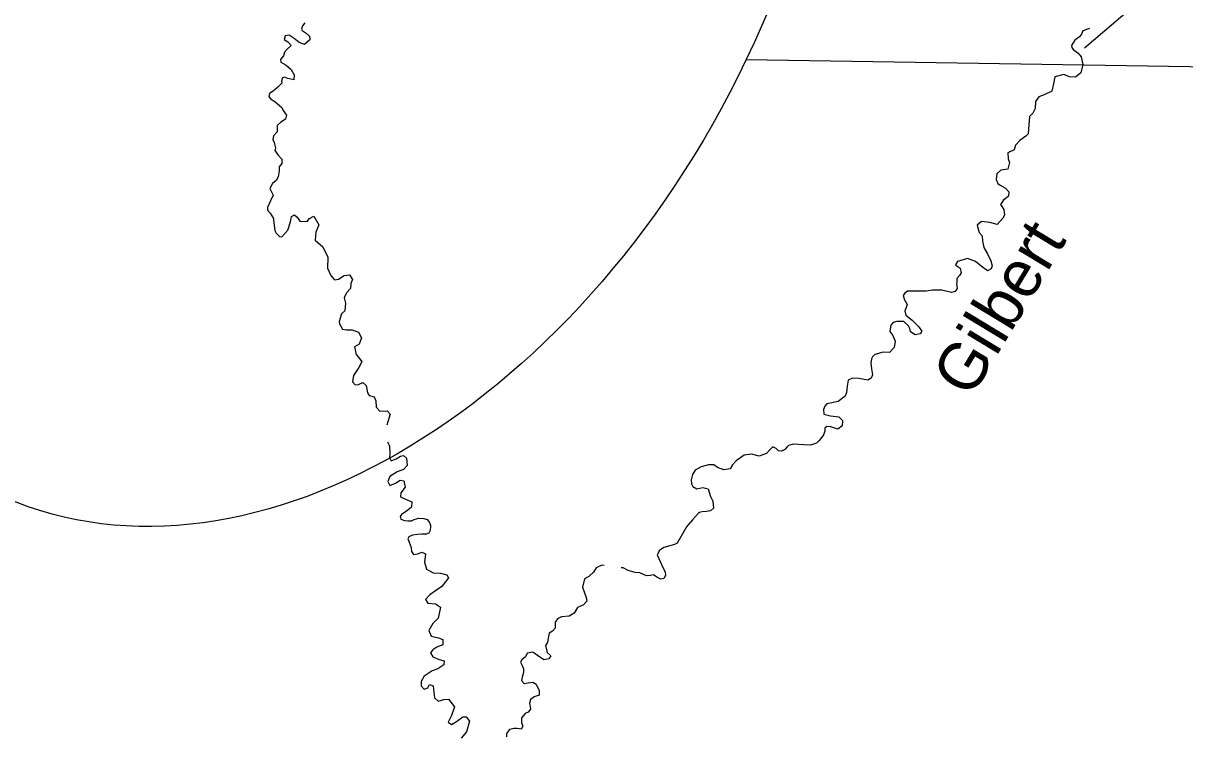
# Model space of a CAD drawing. Extents: x -492261 to -432772, y 1441225 to 1452922.
# Drawn here: x -459623.3 to -459493.5, y 1451796.7 to 1451876.1 of the extents above; entities that cross this region are included whole.
import ezdxf

# ---------------------------------------------------------------- set-up
doc = ezdxf.new("R2010")
doc.units = 0
doc.layers.add('Default', color=7, linetype='Continuous')

msp = doc.modelspace()

# ---------------------------------------------------------------- linework, layer by layer
at = {"layer": 'Default'}
for p, q in [((-459499.71, 1451877.6), (-459504.74, 1451873.32)), ((-459542.51, 1451872.05), (-459085.31, 1451864.81))]:
    msp.add_line(p, q, dxfattribs=at)
for points in [[(-459591.82, 1451876.14), (-459592.08, 1451875.81), (-459592.18, 1451875.45), (-459592.11, 1451875.29), (-459591.66, 1451875.01), (-459591.28, 1451874.67), (-459591.24, 1451874.24), (-459591.86, 1451873.75), (-459592.45, 1451873.97), (-459592.98, 1451874.41), (-459593.55, 1451874.78), (-459594.01, 1451874.7), (-459594.12, 1451874.3), (-459593.69, 1451874.02), (-459593.34, 1451873.63), (-459593.77, 1451873.2), (-459594.09, 1451872.88), (-459594.19, 1451872.45), (-459594.54, 1451872.07), (-459594.48, 1451871.75), (-459593.9, 1451871.42), (-459593.32, 1451870.94), (-459593.01, 1451870.35), (-459593.02, 1451869.78), (-459593.72, 1451869.92), (-459594.07, 1451870.08), (-459594.29, 1451870.01), (-459594.42, 1451869.65), (-459594.39, 1451869.41), (-459594.81, 1451868.95), (-459595.35, 1451868.53), (-459595.75, 1451868.27), (-459595.84, 1451867.92), (-459595.64, 1451867.65), (-459595.15, 1451867.36), (-459594.36, 1451866.71), (-459594.21, 1451866.37), (-459593.86, 1451865.86), (-459593.96, 1451865.39), (-459594.48, 1451865.07), (-459594.89, 1451864.67)], [(-459504.18, 1451875.53), (-459504.92, 1451875.27), (-459505.08, 1451874.9), (-459505.3, 1451874.57), (-459505.81, 1451874.21), (-459506.19, 1451873.62), (-459506.14, 1451873.4), (-459506, 1451873.16), (-459505.45, 1451872.75), (-459505.13, 1451872.34), (-459504.93, 1451871.49), (-459505.16, 1451870.57), (-459505.76, 1451870.09), (-459506.41, 1451870.11), (-459507.06, 1451870.37), (-459508.05, 1451870.12), (-459508.2, 1451869.33), (-459508.38, 1451868.53), (-459509.26, 1451868.11), (-459509.84, 1451867.9), (-459510.23, 1451867.37), (-459510.24, 1451866.58), (-459510.52, 1451866.07), (-459510.88, 1451865.68), (-459510.94, 1451864.75), (-459511.02, 1451863.76), (-459511.28, 1451863.48), (-459511.97, 1451863.01), (-459512.43, 1451862.49), (-459512.61, 1451861.98), (-459513.29, 1451861.65), (-459513.25, 1451860.95), (-459513.1, 1451860.56), (-459513.31, 1451859.83), (-459514.08, 1451859.72), (-459514.54, 1451859.29), (-459514.59, 1451858.67), (-459514.42, 1451858.22), (-459514.17, 1451858.03), (-459513.55, 1451857.68), (-459513.18, 1451857.29), (-459513.24, 1451856.8), (-459513.82, 1451856.33), (-459514.13, 1451855.87), (-459513.75, 1451855.32), (-459513.66, 1451854.68), (-459513.85, 1451854.35), (-459514.5, 1451853.64), (-459515.33, 1451853.85), (-459516.26, 1451853.96), (-459516.72, 1451853.57), (-459516.49, 1451852.73), (-459516.17, 1451852.36), (-459516.15, 1451851.77), (-459515.97, 1451851.07), (-459515.57, 1451850.37), (-459515.2, 1451849.57), (-459515.07, 1451849.02), (-459515.17, 1451848.67), (-459515.58, 1451848.46), (-459516.29, 1451848.97), (-459516.9, 1451849.52), (-459517.79, 1451849.85), (-459518.94, 1451849.49), (-459519.13, 1451849.15), (-459518.95, 1451848.97), (-459518.64, 1451848.76), (-459518.52, 1451848.25), (-459518.7, 1451847.94), (-459519, 1451847.6), (-459519, 1451847.17), (-459519.02, 1451847.02), (-459518.97, 1451846.49), (-459519.18, 1451846.15), (-459519.6, 1451846.06), (-459520.66, 1451846.29), (-459521.71, 1451846.32), (-459522.42, 1451846.19), (-459523.69, 1451846.18), (-459524.49, 1451846.19), (-459524.83, 1451845.95), (-459524.99, 1451845.7), (-459524.84, 1451845.23), (-459524.56, 1451844.7), (-459524.67, 1451844.36), (-459524.81, 1451843.98), (-459524.68, 1451843.53)], [(-459594.89, 1451864.67), (-459594.89, 1451863.97), (-459595.29, 1451863.55), (-459595.38, 1451863.13), (-459595.24, 1451862.78), (-459595.1, 1451862.2), (-459595.15, 1451861.88), (-459594.79, 1451861.37), (-459594.38, 1451860.94), (-459594.38, 1451860.44), (-459594.69, 1451860.06), (-459594.69, 1451859.63), (-459594.8, 1451858.94), (-459595.01, 1451858.56), (-459595.42, 1451858.22), (-459595.73, 1451857.65), (-459595.5, 1451857.19), (-459595.34, 1451856.92), (-459595.63, 1451856.27), (-459595.98, 1451855.52), (-459595.99, 1451855.23), (-459595.66, 1451854.91), (-459595.3, 1451854.3), (-459595.3, 1451854.13), (-459595.16, 1451852.97), (-459595.02, 1451852.68), (-459594.64, 1451852.28), (-459594.36, 1451852.27), (-459593.69, 1451853.01), (-459593.42, 1451853.95), (-459593.28, 1451854.51), (-459592.96, 1451854.72), (-459592.67, 1451854.44), (-459592.37, 1451854), (-459591.54, 1451853.97), (-459591.29, 1451854.29), (-459590.79, 1451854.58), (-459590.24, 1451853.61), (-459590.56, 1451852.79), (-459590.65, 1451851.88), (-459589.79, 1451851.15), (-459589.22, 1451849.97), (-459589.26, 1451848.77), (-459588.89, 1451847.94), (-459588.48, 1451847.44), (-459588.05, 1451847.53), (-459587.41, 1451847.93), (-459586.81, 1451848.01), (-459586.5, 1451847.48), (-459586.67, 1451847.04), (-459586.71, 1451846.48), (-459587.16, 1451846.02), (-459587.4, 1451845.46), (-459587.26, 1451844.85), (-459587.33, 1451843.99), (-459587.7, 1451843.68), (-459587.97, 1451842.79), (-459587.94, 1451842.56), (-459587.61, 1451841.95), (-459587.15, 1451841.89), (-459586.52, 1451841.89), (-459585.81, 1451841.62), (-459585.49, 1451841), (-459585.74, 1451840.26), (-459586.27, 1451839.98), (-459586.07, 1451839.11), (-459585.81, 1451838.82), (-459585.44, 1451838.29), (-459585.76, 1451837.67), (-459586.39, 1451836.78), (-459586.47, 1451836.06), (-459586.2, 1451835.73), (-459585.8, 1451835.78), (-459585.34, 1451835.98), (-459584.97, 1451835.65), (-459584.81, 1451834.83), (-459584.63, 1451834.55), (-459584.07, 1451834.41), (-459583.86, 1451833.93), (-459583.83, 1451833.24), (-459583.42, 1451832.81), (-459582.61, 1451832.84), (-459582.27, 1451832.46), (-459582.54, 1451831.62), (-459582.66, 1451831.24)], [(-459524.68, 1451843.53), (-459524, 1451842.96), (-459523.28, 1451842.25), (-459522.92, 1451841.72), (-459523.11, 1451841.44), (-459523.66, 1451841.33), (-459524.17, 1451841.65), (-459524.24, 1451842.03), (-459524.38, 1451842.32), (-459524.9, 1451842.8), (-459525.68, 1451842.81), (-459526.11, 1451842.68), (-459526.37, 1451842.41), (-459526.49, 1451841.68), (-459526.16, 1451841.23), (-459525.87, 1451840.6), (-459526.01, 1451839.9), (-459526.52, 1451839.34), (-459527.22, 1451839.38), (-459528.15, 1451839.11), (-459528.42, 1451838.87), (-459528.51, 1451838.65), (-459528.61, 1451838.16), (-459528.54, 1451837.52), (-459528.41, 1451836.84), (-459528.55, 1451836.48), (-459528.95, 1451836.27), (-459529.95, 1451836.44), (-459530.64, 1451836.47), (-459531.12, 1451836.27), (-459531.24, 1451835.58), (-459531.31, 1451834.86), (-459531.45, 1451834.47), (-459532.26, 1451833.89), (-459533.51, 1451833.6), (-459533.73, 1451833.34), (-459533.89, 1451832.98), (-459533.84, 1451832.45), (-459533.09, 1451832.28), (-459532.19, 1451832.18), (-459531.78, 1451831.74), (-459531.79, 1451831.15), (-459532.27, 1451830.78), (-459533.07, 1451831.04), (-459533.52, 1451831.1), (-459533.75, 1451830.91), (-459533.75, 1451830.56), (-459533.89, 1451830.17), (-459534.17, 1451829.73), (-459534.4, 1451829.49), (-459534.67, 1451829.24), (-459535.33, 1451828.99), (-459536.07, 1451829.04), (-459537.22, 1451829.1), (-459537.81, 1451828.96), (-459537.95, 1451828.81), (-459538.22, 1451828.51), (-459538.58, 1451828.32), (-459538.93, 1451828.35), (-459539.19, 1451828.64), (-459539.54, 1451828.8), (-459539.93, 1451828.45), (-459540.25, 1451828.08), (-459541.07, 1451827.78), (-459541.91, 1451828.01), (-459542.75, 1451827.9), (-459543.64, 1451827.25), (-459544.04, 1451826.79), (-459544.3, 1451826.36), (-459545.03, 1451826.23), (-459545.71, 1451826.52), (-459546.13, 1451826.79), (-459546.73, 1451826.8), (-459547.55, 1451826.58), (-459548.2, 1451826.22), (-459548.5, 1451825.71), (-459548.66, 1451825.14), (-459548.62, 1451824.68), (-459548.49, 1451824.4), (-459548.03, 1451824.12), (-459547.38, 1451824.26), (-459546.78, 1451824.11), (-459546.52, 1451823.27), (-459546.25, 1451822.73), (-459546.16, 1451821.98), (-459546.49, 1451821.66), (-459546.96, 1451821.61), (-459547.45, 1451821.57), (-459547.72, 1451821.48), (-459547.85, 1451821.39), (-459548.53, 1451820.68), (-459549, 1451820.12), (-459549.2, 1451819.87)], [(-459582.57, 1451829.37), (-459582.36, 1451828.94), (-459582.31, 1451828.06), (-459582.37, 1451827.61), (-459582.15, 1451827.25), (-459581.62, 1451827.47), (-459581.12, 1451827.78), (-459580.79, 1451827.83), (-459580.46, 1451827.55), (-459580.38, 1451826.74), (-459580.8, 1451826.28), (-459581.51, 1451826.02), (-459582.31, 1451825.5), (-459582.54, 1451824.95)], [(-459582.54, 1451824.95), (-459582.33, 1451824.51), (-459581.69, 1451824.74), (-459581.16, 1451825.08), (-459580.74, 1451825), (-459580.6, 1451824.3), (-459581.1, 1451823.66), (-459581.11, 1451823.23), (-459580.58, 1451822.97), (-459579.87, 1451822.68), (-459579.91, 1451822.07), (-459580.49, 1451821.59), (-459581.01, 1451821.27), (-459581.17, 1451821.04), (-459581.07, 1451820.74), (-459580.68, 1451820.59), (-459580.32, 1451820.54), (-459579.89, 1451820.54), (-459579.6, 1451820.71), (-459579.07, 1451820.83), (-459578.52, 1451820.81), (-459578.14, 1451820.7), (-459577.91, 1451820.45), (-459577.77, 1451820.06), (-459577.77, 1451819.81), (-459577.8, 1451819.59), (-459577.86, 1451819.39), (-459577.97, 1451819.16)], [(-459549.2, 1451819.87), (-459550.22, 1451818.06), (-459550.51, 1451817.92), (-459551.03, 1451817.77), (-459551.7, 1451817.56), (-459552.21, 1451817.23), (-459552.48, 1451816.76), (-459551.78, 1451815.25), (-459551.55, 1451814.85), (-459551.54, 1451814.46), (-459551.72, 1451814.12), (-459552.06, 1451814.02), (-459552.49, 1451814.25), (-459552.88, 1451814.51), (-459553.22, 1451814.46), (-459553.64, 1451814.41), (-459554.41, 1451814.74), (-459554.92, 1451814.79)], [(-459577.97, 1451819.16), (-459578.25, 1451819.06), (-459578.75, 1451819.06), (-459579.22, 1451819.04), (-459579.8, 1451818.96), (-459580.21, 1451818.75), (-459580.31, 1451818.54), (-459580.16, 1451818.18), (-459579.94, 1451817.57), (-459579.88, 1451817.11), (-459579.66, 1451816.81), (-459579.19, 1451816.88), (-459578.75, 1451817.04), (-459578.33, 1451816.85), (-459578.43, 1451815.95), (-459578.23, 1451815.17), (-459577.46, 1451814.73), (-459576.64, 1451814.71), (-459575.94, 1451814.51), (-459575.76, 1451814.18), (-459576.51, 1451813.22), (-459577.23, 1451812.75), (-459577.83, 1451812.29), (-459578.35, 1451811.75), (-459578.08, 1451811.34), (-459577.23, 1451811.3), (-459576.66, 1451810.9), (-459576.92, 1451809.69), (-459577.5, 1451809.08), (-459577.96, 1451808.29), (-459577.69, 1451807.67), (-459576.88, 1451807.5), (-459576.41, 1451807.29), (-459576.41, 1451806.7), (-459577.05, 1451806.45), (-459577.51, 1451806.16), (-459577.76, 1451805.83), (-459577.53, 1451805.38), (-459576.81, 1451805.07), (-459576.23, 1451804.92), (-459576.28, 1451804.48), (-459576.95, 1451804.04), (-459577.59, 1451803.81), (-459578.48, 1451803.22), (-459578.8, 1451802.62), (-459578.8, 1451802.12), (-459578.47, 1451801.76), (-459578.06, 1451801.92), (-459577.89, 1451802.29), (-459577.49, 1451802.13), (-459577.42, 1451801.4), (-459577.31, 1451800.77), (-459576.9, 1451800.42), (-459576.27, 1451800.61), (-459575.77, 1451800.63), (-459575.11, 1451799.78), (-459575.42, 1451798.81), (-459575.79, 1451798.08), (-459575.42, 1451797.8), (-459574.88, 1451798.14), (-459574.18, 1451798.65), (-459573.8, 1451798.66), (-459573.42, 1451798.18), (-459573.75, 1451796.99), (-459574.35, 1451796.29)], [(-459558.37, 1451815.58), (-459558.64, 1451815.59), (-459559.26, 1451815.3), (-459559.59, 1451814.82)], [(-459554.92, 1451814.79), (-459555.7, 1451814.99), (-459556.27, 1451815.3), (-459556.48, 1451815.31)], [(-459559.59, 1451814.82), (-459560.1, 1451814.35), (-459560.56, 1451814.09), (-459560.8, 1451813.14), (-459560.39, 1451811.98), (-459560.33, 1451811.58), (-459560.7, 1451811.16), (-459561.34, 1451810.86), (-459561.73, 1451810.26), (-459562.29, 1451809.91), (-459563.15, 1451809.82), (-459563.61, 1451809.61), (-459563.85, 1451809.23), (-459563.86, 1451808.58), (-459564.15, 1451808.22), (-459564.52, 1451807.99), (-459564.64, 1451807.46), (-459564.72, 1451806.95), (-459564.92, 1451806.62), (-459564.74, 1451805.84), (-459564.34, 1451805.48), (-459564.57, 1451805.13), (-459565.12, 1451805.04), (-459565.84, 1451805.51), (-459566.36, 1451805.88), (-459566.97, 1451805.77), (-459567.18, 1451805.35), (-459567.58, 1451805.04), (-459567.73, 1451804.78), (-459567.54, 1451804.38), (-459567.38, 1451804.01), (-459567.39, 1451803.62), (-459567.55, 1451803.09), (-459567.62, 1451802.72), (-459567.33, 1451802.4), (-459566.88, 1451802.46), (-459566.35, 1451802.53), (-459565.98, 1451802.33), (-459565.63, 1451801.6), (-459565.64, 1451801.09), (-459566.18, 1451800.89), (-459566.59, 1451800.59), (-459566.71, 1451800.21), (-459566.6, 1451799.54), (-459566.85, 1451799.17), (-459567.22, 1451799.03), (-459567.62, 1451798.57), (-459567.63, 1451798.01), (-459567.45, 1451797.62), (-459567.65, 1451797.3), (-459568.11, 1451797.38), (-459568.44, 1451797.36), (-459568.95, 1451797.24), (-459569.27, 1451796.82), (-459569.27, 1451796.45)]]:
    msp.add_lwpolyline(points, dxfattribs=at)
msp.add_ellipse((-459592.08, 1451895.81), major_axis=(-34.55, -72.06), ratio=0.687937, dxfattribs=at)

# ---------------------------------------------------------------- texts
msp.add_text('Gilbert', height=5.28, rotation=58.8178, dxfattribs=at).set_placement((-459517.46, 1451834.11))

doc.saveas('drawing.dxf')
